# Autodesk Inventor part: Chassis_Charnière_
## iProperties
Created: 2009-01
Part Number: Chassis_Charnière_
Document SubType Name: Modeling
Designer: claivier
Author: claivier
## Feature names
1. Extrusion1
2. Extrusion2
3. Réseau rectangulaire1 [Rectangular Pattern]
4. Perçage2 [Hole]
